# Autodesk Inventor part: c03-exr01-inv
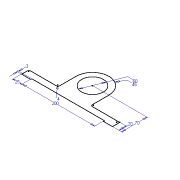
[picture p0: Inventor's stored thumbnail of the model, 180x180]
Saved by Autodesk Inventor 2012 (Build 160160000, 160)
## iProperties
Shininess: 64.0
Length Units: 11269
Angle Units: 11279
Time Units: 11290
Mass Units: 11283
Length Display Precision: 3
Angle Display Precision: 2
Compacted: True
Created: 2002-02
Part Number: c03-exr01-inv
Document SubType Name: Modeling
Density: 1 g/cm^3
Material: Default
Density: 0.0
Volumn: 0.0
Area: 0.0
PropertySet Name: Model Information
Control State: 0
Master: False
Checked Out: False
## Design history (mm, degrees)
sketch "Sketch1"
  geometry: L1 (-47.967, -16.304)-(-119.967, -16.304); L2 (-123.967, -20.304)-(-123.967, -36.304); L3 (-123.967, -36.304)-(-98.967, -36.304); L4 (-98.967, -36.304)-(-98.967, -33.304); L5 (-98.967, -33.304)-(101.033, -33.304); L6 (101.033, -33.304)-(101.033, -36.304); L7 (101.033, -36.304)-(126.033, -36.304); L8 (126.033, -36.304)-(126.033, -20.304); L9 (122.033, -16.304)-(50.033, -16.304); L10 (46.033, -12.304)-(46.033, 33.696); L11 (-43.967, 33.696)-(-43.967, -12.304); C1 r 30 at (1.033, 33.696); A1 r 45 centre (1.033, 33.696) between (46.033, 33.696) and (-43.967, 33.696); A2 r 4 centre (-47.967, -12.304) between (-47.967, -16.304) and (-43.967, -12.304); A3 r 4 centre (50.033, -12.304) between (46.033, -12.304) and (50.033, -16.304); A4 r 4 centre (122.033, -20.304) between (126.033, -20.304) and (122.033, -16.304); A5 r 4 centre (-119.967, -20.304) between (-119.967, -16.304) and (-123.967, -20.304); 1 further point
  constraints: 22 end point, 10 point on circle, 10 tangent, 8 parallel, 6 centre point, 4 equal length, 3 equal radius, 2 point on line, 1 coincident, 1 collinear, 1 horizontal, 1 perpendicular
  dimensions: "d0" = 25 distance of L2.end L3.end; "d1" = 200 distance of L4.end L5.end; "d2" = 3 distance of L3.end L4.end; "d3" = 20 distance of L7.end point (126.033, -16.304); "d4" = 70 distance from line of A1.centre L7; "d5" = 45 radius of A1; "d6" = 4 radius of A2; "d7" = 60 diameter of C1
